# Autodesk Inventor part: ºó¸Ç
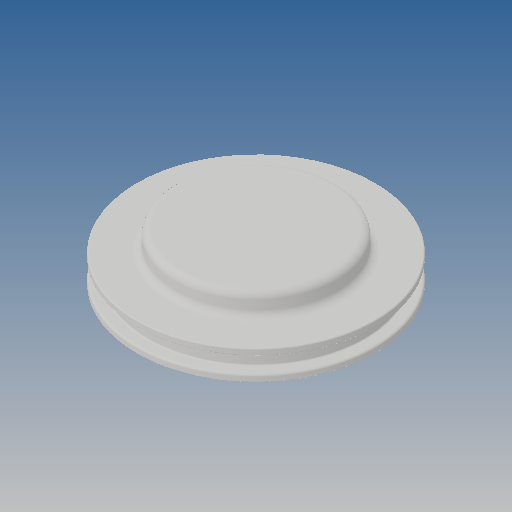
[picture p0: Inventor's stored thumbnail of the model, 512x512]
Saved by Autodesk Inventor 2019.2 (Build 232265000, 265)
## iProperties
Created: 2013-07
Part Number: ºó¸Ç
Material: Ogólny
Document SubType Name: Modeling
Designer: CADENGINEERING4
Density: 1 g/cm^3
Appearance: Domyślna
Author: CADENGINEERING4
Revision Number: ÈÎºÎ
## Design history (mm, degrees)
feature "Ðý×ª2"
node "Bryła1"
